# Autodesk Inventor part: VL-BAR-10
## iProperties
Created: 2005-08
Part Number: VL-BAR-10
Document SubType Name: Sheet Metal
Density: 1 g/cm^3
Mass: 1.69074 g
Surface Area: 32.8008 cm^2
Volume: 1.69074 cm^3
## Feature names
1. Rectangular Pattern1
2. Plate1
